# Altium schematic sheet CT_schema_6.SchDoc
size 405 x 220 mm
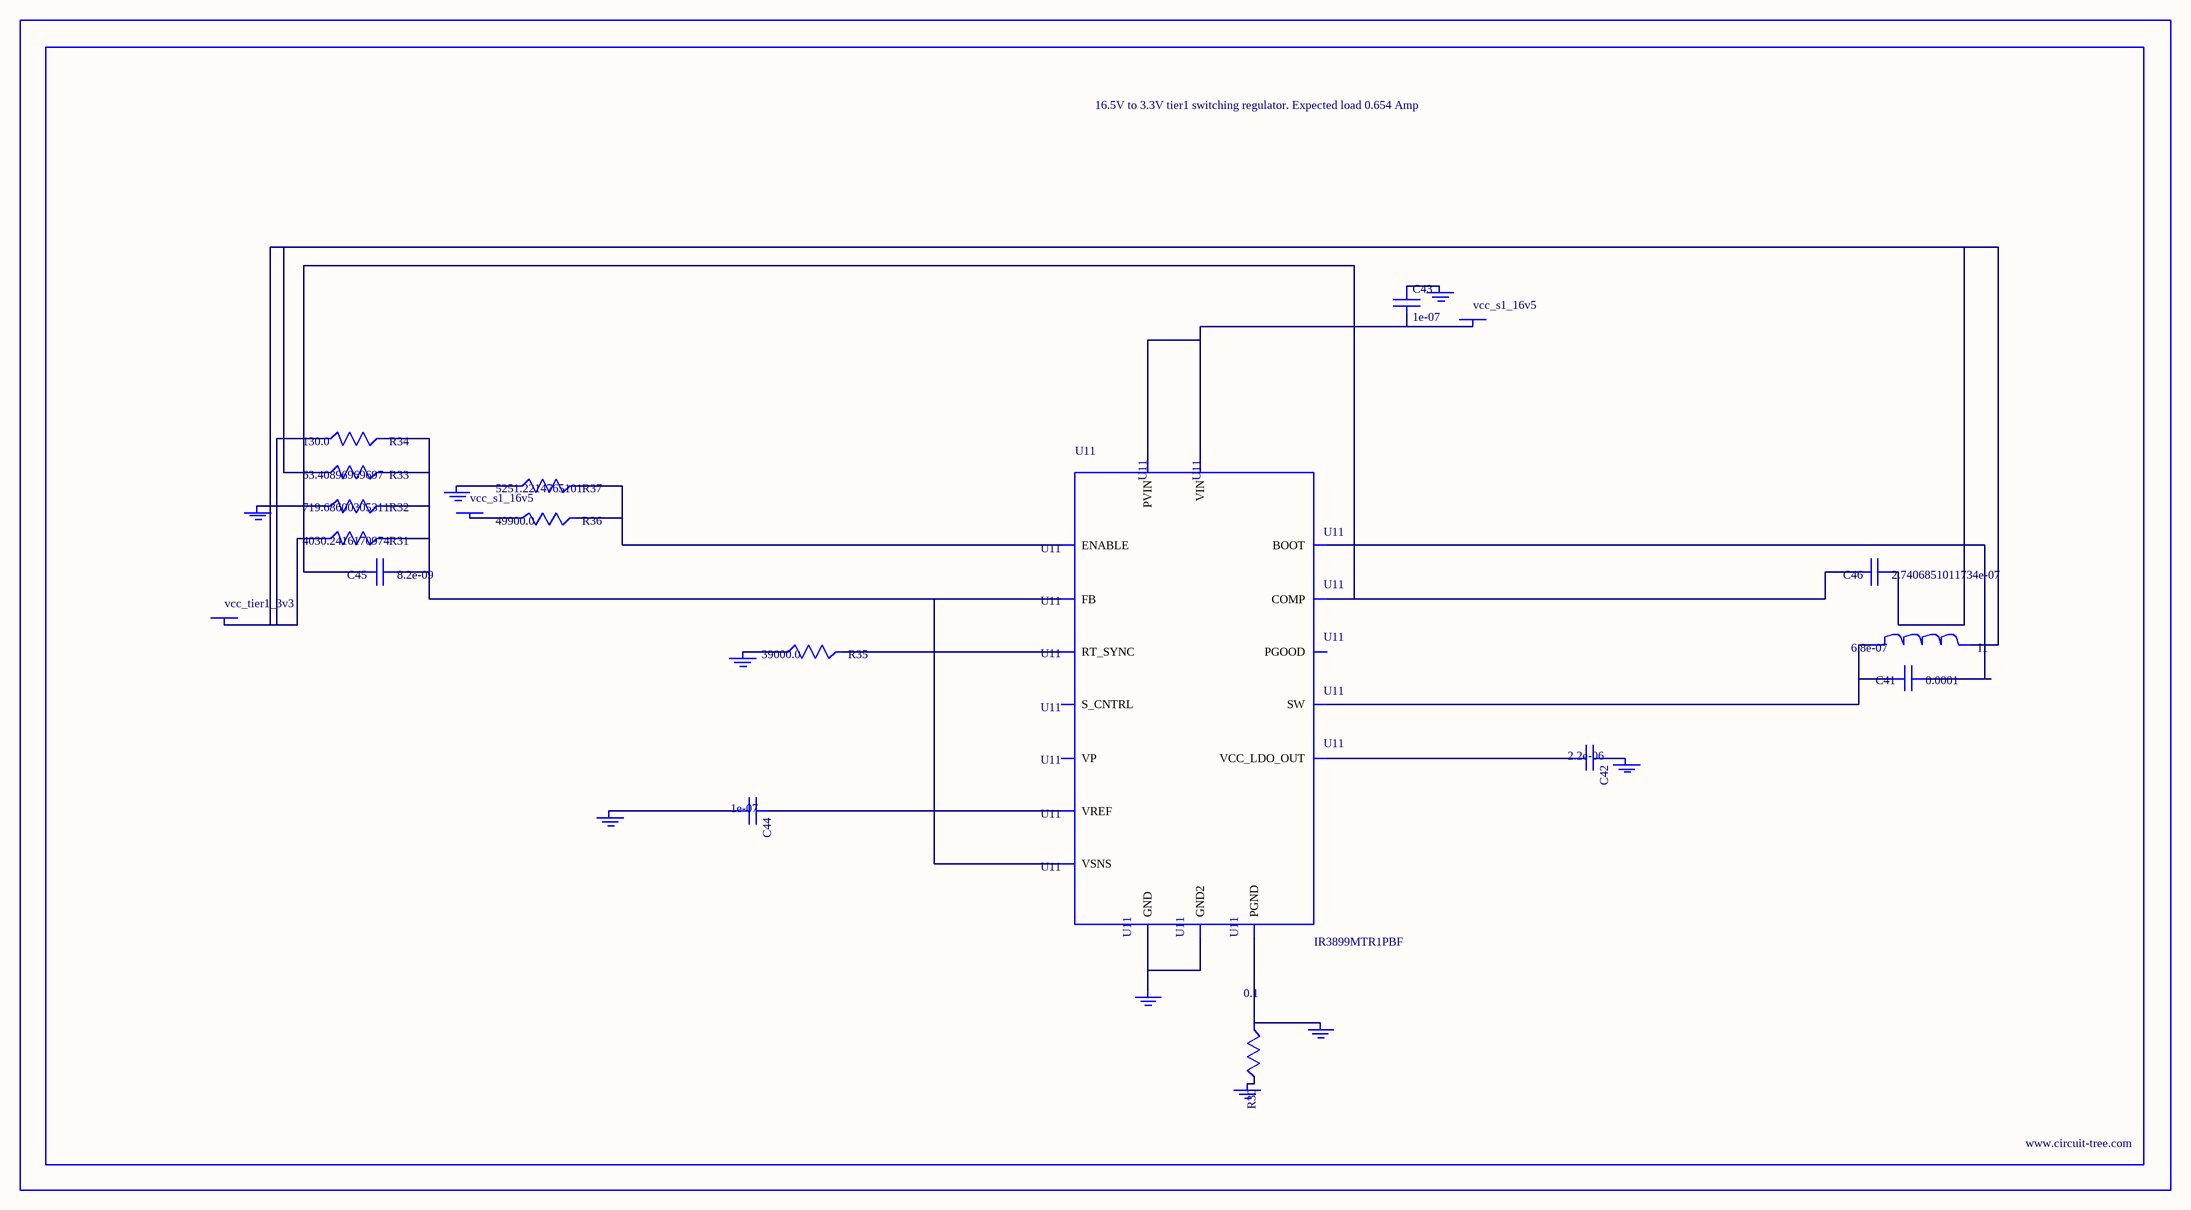
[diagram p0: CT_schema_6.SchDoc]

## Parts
BORDER5  (no value)
C41  0.0001  [C1210]
C42  2.2e-06  [C0603]
C43  1e-07  [C0402]
C44  1e-07  [C0402]
C45  8.2e-09  [C0402]
C46  2.7406851011734e-07  [R0603]
GND_INSTANCE_5_0  (no value)
GND_INSTANCE_5_1  (no value)
GND_INSTANCE_5_2  (no value)
GND_INSTANCE_5_3  (no value)
GND_INSTANCE_5_4  (no value)
GND_INSTANCE_5_5  (no value)
GND_INSTANCE_5_6  (no value)
GND_INSTANCE_5_7  (no value)
GND_INSTANCE_5_8  (no value)
I1  6.8e-07  [IND25X25CZ]
POWER_INSTANCE_5_0  vcc_s1_16v5
POWER_INSTANCE_5_1  vcc_s1_16v5
POWER_INSTANCE_5_2  vcc_tier1_3v3
R30  0.1  [R0603]
R31  4030.2416170974  [R0603]
R32  719.68600305311  [R0603]
R33  63.40896969697  [R0603]
R34  130.0  [R0603]
R35  39000.0  [R0603]
R36  49900.0  [R0603]
R37  5251.2214765101  [R0603]
U11  IR3899MTR1PBF  [IR3899MTR1PBF]

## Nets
NetC41_1: C41.1 U11.14(BOOT)
NetC41_2: C41.2 I1.1 U11.12(SW)
NetC42_1: C42.1 GND_INSTANCE_5_4.0(GND)
NetC42_2: C42.2 U11.10(VCC_LDO_OUT)
NetC43_1: C43.1 GND_INSTANCE_5_3.0(GND)
NetC43_2: C43.2 POWER_INSTANCE_5_0.0(PWR) U11.9(VIN) U11.13(PVIN)
NetC44_1: C44.1 U11.2(VREF)
NetC44_2: C44.2 GND_INSTANCE_5_1.0(GND)
NetC45_1: C45.1 R31.2 R32.2 R33.2 R34.2 U11.1(FB) U11.8(VSNS)
NetC45_2: C45.2 C46.2 U11.3(COMP)
NetC46_1: C46.1 I1.2 POWER_INSTANCE_5_2.0(PWR) R31.1 R33.1 R34.1
NetGND_INSTANCE_5_0_0: GND_INSTANCE_5_0.0(GND) R32.1
NetGND_INSTANCE_5_2_0: GND_INSTANCE_5_2.0(GND) R35.1
NetGND_INSTANCE_5_5_0: GND_INSTANCE_5_5.0(GND) R30.2
NetGND_INSTANCE_5_6_0: GND_INSTANCE_5_6.0(GND) R30.1 U11.11(PGND)
NetGND_INSTANCE_5_7_0: GND_INSTANCE_5_7.0(GND) R37.1
NetGND_INSTANCE_5_8_0: GND_INSTANCE_5_8.0(GND) U11.4(GND) U11.17(GND2)
NetPOWER_INSTANCE_5_1_0: POWER_INSTANCE_5_1.0(PWR) R36.1
NetR35_2: R35.2 U11.5(RT_SYNC)
NetR36_2: R36.2 R37.2 U11.15(ENABLE)

Not connected (* = marked no-connect by the designer): U11 6(S_CNTRL) 7(PGOOD) 16(VP)

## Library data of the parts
BORDER5 = BORDER_PAGE5
C41 = GRM32ER61A107ME20L
C42 = C0603C225K8RACTU
C43 C44 = C0402C104K3RACTU
C45 = C0402C822K3RAC
C46 = C46
GND_INSTANCE_5_0-GND_INSTANCE_5_8 = GND
I1 = IHLP2525CZERR68M01
POWER_INSTANCE_5_0-POWER_INSTANCE_5_2 = PWR
R30 = ERJ-3RSFR10V
R31 = R31
R32 = R32
R33 = R33
R34 = RC0603JR-07130RL
R35 = RC0603JR-0739KL
R36 = RC0603FR-0749K9
R37 = R37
